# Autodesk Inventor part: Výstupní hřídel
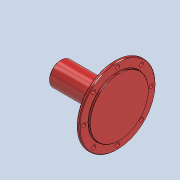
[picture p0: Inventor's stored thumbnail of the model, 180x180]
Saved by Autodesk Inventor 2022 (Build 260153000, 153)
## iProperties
Created: 2025-05
Part Number: Výstupní hřídel
Material: Všeobecné
Document SubType Name: Modeling
Designer: jbart
Density: 1 g/cm^3
Appearance: Oranžovo-červená
Mass: 1634.63 g
Surface Area: 1615.74 cm^2
Volume: 1634.63 cm^3
Author: jbart
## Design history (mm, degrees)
sketch "Náčrt1"
  geometry: L1 (0, 0)-(200, 0); L2 (194, 130)-(194, 100); L3 (194, 100)-(200, 100); L4 (200, 100)-(200, 0); L5 (194, 130)-(184, 130); L6 (184, 130)-(184, 40); L7 (184, 40)-(0, 40); L8 (0, 40)-(0, 0); 1 further point
  constraints: 16 end point, 5 perpendicular, 2 horizontal, 1 midpoint, 1 point on line, 1 vertical, 1 vertical alignment
  dimensions: "d0" = 200 distance of L1.start L1.end; "d2" = 6 distance of L2.end L3.end; "d3" = 10 distance of L2.start L5.end; "d4" = 200 diameter of L3 L1; "d5" = 260 diameter of L5 L1; "d6" = 80 diameter of L7 L1
revolve "Rotace1" sketch "Náčrt1" stored, may be unused: angle "d7" = 90 deg
fillet "Zaoblení1" dims "d8" = 10
sketch "Náčrt2" dims "d9" = 230
  geometry: L1 (0, 0)-(0, 115); 2 further points
  constraints: 2 coincident, 2 end point, 1 vertical, 1 vertical alignment, 2 other
hole "Díra1" sketch "Náčrt2" at (0, 115) diameter "d10" = 13.5; stored, may be unused: countersink angle "d14" = 90 deg, drill point angle "d16" = 118 deg; dims "d11" = 15, "d12" = 4, "d13" = 2, "d15" = 20
pattern_circular "Kruhové pole1" dims angle "d18" = 360 deg
chamfer "Zkosení1" distance "d20" = 2; stored, may be unused: second distance "d21" = 2, angle "d22" = 45 deg
chamfer "Zkosení2" distance "d23" = 1; stored, may be unused: second distance "d24" = 2, angle "d25" = 45 deg
fillet "Zaoblení2" dims "d26" = 1
node "Těleso1"
